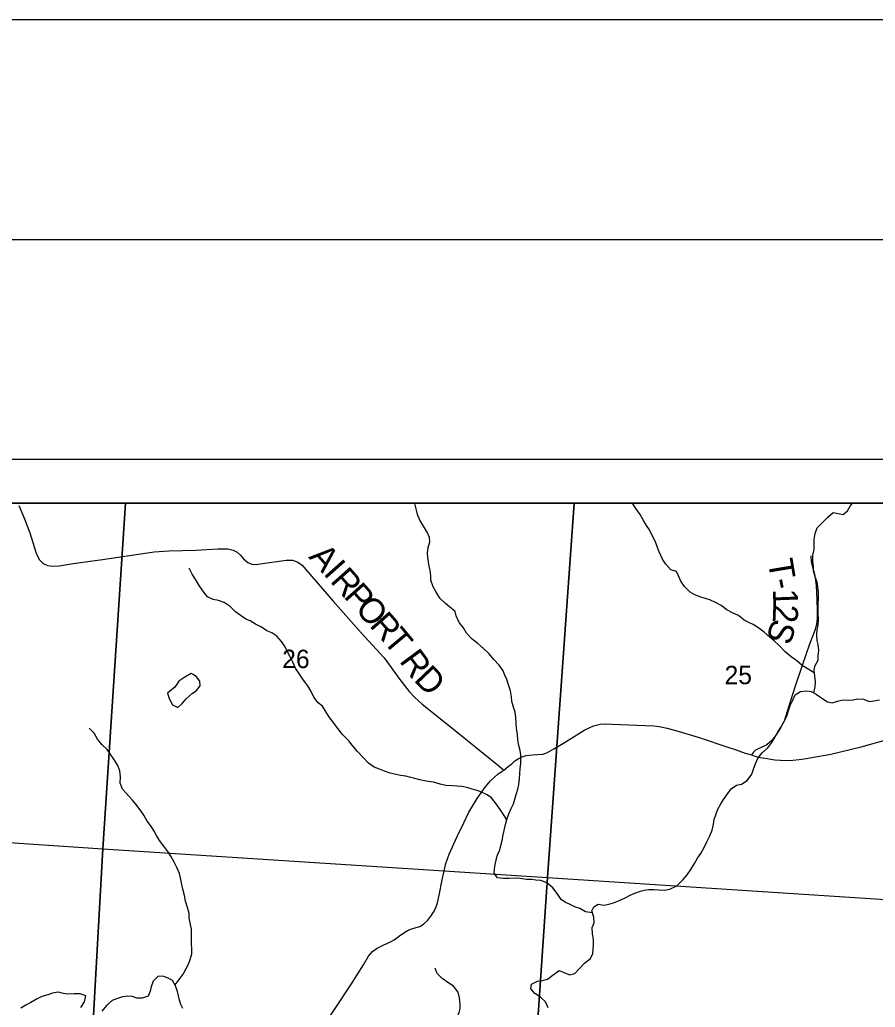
# Model space of a CAD drawing. Extents: x 0 to 34, y 0 to 22.
# Drawn here: x 3.268 to 5.215, y 19.753 to 22 of the extents above; entities that cross this region are included whole.
import ezdxf

# ---------------------------------------------------------------- set-up
doc = ezdxf.new("R2010")
doc.units = 0
for name, color, linetype in [('Default', 7, 'Continuous'), ('GM_X_County_Road', 7, 'Continuous'), ('GM_X_County_Road_Text', 7, 'Continuous'), ('GM_X_Major_River', 7, 'Continuous'), ('GM_X_Minor_Lake', 7, 'Continuous'), ('GM_X_Minor_River', 7, 'Continuous'), ('GM_X_Section', 7, 'Continuous'), ('GM_X_Section_Text', 7, 'Continuous'), ('GM_X_State_Route', 7, 'Continuous'), ('GM_X_Township_Road', 7, 'Continuous'), ('GM_X_Township_Road_Text', 7, 'Continuous'), ('SC_Scratch1', 7, 'Continuous'), ('SH_Border', 7, 'Continuous'), ('SH_Cut_Line', 7, 'Continuous'), ('SH_Data', 7, 'Continuous')]:
    doc.layers.add(name, color=color, linetype=linetype)

msp = doc.modelspace()

# ---------------------------------------------------------------- linework, layer by layer
at = {"layer": 'Default'}
for points in [[(3.5087, 20.9), (2.4999, 20.9), (2.446, 20.1823), (3.4572, 20.1141)], [(4.5292, 20.9), (3.5087, 20.9), (3.4572, 20.1141), (4.4687, 20.0485)], [(5.5445, 20.9), (4.5292, 20.9), (4.4687, 20.0485), (5.483, 19.983)]]:
    msp.add_lwpolyline(points, close=True, dxfattribs=at)
at = {"layer": 'GM_X_County_Road'}
msp.add_lwpolyline([(3.2658, 20.8947), (3.279, 20.8648), (3.2905, 20.8326), (3.3047, 20.7887), (3.3089, 20.7781), (3.3128, 20.7712), (3.3208, 20.7632), (3.3309, 20.7583), (3.342, 20.7567), (3.3576, 20.7579), (3.3896, 20.7629), (3.4561, 20.7721), (3.5736, 20.7892), (3.6077, 20.7921), (3.6686, 20.7933), (3.7197, 20.7965), (3.7413, 20.7965), (3.7533, 20.7935), (3.7623, 20.7889), (3.7699, 20.7818), (3.7768, 20.7738), (3.7867, 20.765), (3.7961, 20.7618), (3.8062, 20.7606), (3.8205, 20.7627), (3.8738, 20.7705), (3.8888, 20.7705), (3.8991, 20.7671), (3.9056, 20.7632), (3.9111, 20.7581), (3.9182, 20.7501), (3.9813, 20.6774), (4.0448, 20.6051), (4.097, 20.5485), (4.1326, 20.4989), (4.1538, 20.4719), (4.1667, 20.4579), (4.1839, 20.4429), (4.2511, 20.3889), (4.3578, 20.3024), (4.3692, 20.2929)], dxfattribs=at)
at = {"layer": 'GM_X_Major_River'}
for points in [[(4.4403, 19.7844), (4.4313, 19.7955), (4.4328, 19.8057), (4.4465, 19.8124), (4.4564, 19.8143), (4.469, 19.8176), (4.4819, 19.827), (4.4956, 19.8367), (4.51, 19.8306), (4.5198, 19.8275), (4.5309, 19.83), (4.5412, 19.841), (4.553, 19.8534), (4.5668, 19.8647), (4.5718, 19.8756), (4.573, 19.8859), (4.5734, 19.8961), (4.5739, 19.9082), (4.5713, 19.9208), (4.5703, 19.9352), (4.5749, 19.9458), (4.5746, 19.9583), (4.5701, 19.9724), (4.574, 19.9822), (4.5839, 19.9882), (4.5971, 19.9854), (4.6085, 19.988), (4.6192, 19.9913), (4.634, 19.9969), (4.6469, 20.0029), (4.6568, 20.0081), (4.6675, 20.0126), (4.6781, 20.0167), (4.6888, 20.0197), (4.6987, 20.0211), (4.7119, 20.0214), (4.7218, 20.0206), (4.7347, 20.0201), (4.7476, 20.0223), (4.7636, 20.0297), (4.7773, 20.044), (4.7869, 20.0546), (4.7949, 20.0671), (4.8034, 20.0803), (4.8106, 20.0927), (4.8175, 20.1033), (4.826, 20.1184), (4.8314, 20.1301), (4.8383, 20.1434), (4.8437, 20.1566), (4.8464, 20.1702), (4.848, 20.1805), (4.8519, 20.1914), (4.8565, 20.2043), (4.8631, 20.216), (4.8692, 20.2258), (4.8768, 20.2368), (4.8868, 20.2503), (4.899, 20.259), (4.9104, 20.2608), (4.9233, 20.269), (4.9337, 20.2838), (4.9379, 20.2951), (4.9433, 20.3095), (4.9487, 20.3208), (4.9575, 20.3321), (4.9701, 20.3434), (4.9793, 20.3555), (4.9881, 20.3702), (4.9939, 20.3804), (5.0008, 20.3914), (5.0069, 20.4027), (5.0134, 20.4156), (5.0173, 20.4284), (5.0208, 20.4398), (5.027, 20.4519), (5.0327, 20.464), (5.0445, 20.4718), (5.059, 20.4733), (5.0688, 20.4717), (5.0802, 20.4659), (5.093, 20.4563), (5.1062, 20.4479), (5.1164, 20.4463), (5.129, 20.4496), (5.1419, 20.4529), (5.1548, 20.4521), (5.1643, 20.4531), (5.1742, 20.4553), (5.1878, 20.4545), (5.2007, 20.4487), (5.2117, 20.4505), (5.2242, 20.4531)], [(4.4704, 19.7523), (4.4644, 19.7657), (4.4528, 19.7764), (4.4403, 19.7844)]]:
    msp.add_lwpolyline(points, dxfattribs=at)
at = {"layer": 'GM_X_Minor_Lake'}
for points in [[(3.6622, 20.5101), (3.6581, 20.5126), (3.6434, 20.5046), (3.6302, 20.4951), (3.6211, 20.4818), (3.6038, 20.4681)], [(3.6038, 20.4681), (3.6076, 20.456), (3.6156, 20.4416), (3.6277, 20.4352), (3.6375, 20.4447), (3.6462, 20.4553), (3.6602, 20.4671), (3.6704, 20.4744), (3.6787, 20.485), (3.6775, 20.4956), (3.6699, 20.5054), (3.6622, 20.5101)]]:
    msp.add_lwpolyline(points, dxfattribs=at)
at = {"layer": 'GM_X_Minor_River'}
for points in [[(4.5715, 19.9681), (4.5555, 19.9704), (4.5423, 19.978), (4.5328, 19.9813), (4.5191, 19.9878), (4.5097, 19.9915), (4.4998, 19.9987), (4.4907, 20.0123), (4.4808, 20.0252), (4.4675, 20.0362), (4.4538, 20.0418), (4.4421, 20.0425), (4.4323, 20.0437), (4.4209, 20.0444), (4.4069, 20.0466), (4.3955, 20.047), (4.3819, 20.0466), (4.3687, 20.0465), (4.3554, 20.0476), (4.3478, 20.0586), (4.3485, 20.0685), (4.35, 20.0779), (4.3523, 20.0882), (4.3545, 20.0977), (4.3601, 20.1117), (4.3627, 20.1212), (4.3657, 20.133), (4.368, 20.1455), (4.3706, 20.1557), (4.3732, 20.169), (4.3766, 20.1804), (4.3811, 20.1937), (4.3859, 20.2058), (4.3912, 20.216), (4.3946, 20.227), (4.3976, 20.2373), (4.4013, 20.2494), (4.4036, 20.2601), (4.405, 20.2741), (4.4061, 20.2847), (4.4068, 20.2965), (4.4083, 20.3082), (4.4083, 20.3177), (4.4079, 20.3275), (4.4067, 20.3378), (4.4036, 20.3488), (4.4013, 20.3609), (4.4005, 20.3745), (4.3986, 20.3878), (4.3978, 20.3988), (4.397, 20.4132), (4.3951, 20.4246), (4.3913, 20.4363), (4.3878, 20.4492), (4.387, 20.4594), (4.3847, 20.4734), (4.3809, 20.4848), (4.3763, 20.4988), (4.3721, 20.5091), (4.3683, 20.5189), (4.3591, 20.5318), (4.347, 20.5443), (4.3356, 20.5583), (4.3231, 20.5692), (4.3105, 20.5806), (4.2973, 20.5911), (4.2847, 20.6044), (4.2775, 20.6169), (4.268, 20.6286), (4.2607, 20.6438), (4.2584, 20.6536), (4.2459, 20.6642), (4.2364, 20.6721), (4.2243, 20.6835), (4.2155, 20.6975), (4.2087, 20.71), (4.2037, 20.7247), (4.2033, 20.735), (4.2017, 20.7471), (4.1998, 20.7566), (4.1979, 20.7664), (4.1963, 20.7763), (4.1956, 20.7865), (4.1974, 20.799), (4.2008, 20.8123), (4.2004, 20.8218), (4.195, 20.8343), (4.187, 20.8479), (4.1787, 20.8612), (4.1729, 20.8744), (4.1706, 20.8843), (4.1668, 20.8994), (4.1667, 20.9)], [(5.0761, 20.5142), (5.0618, 20.5229), (5.0485, 20.5312), (5.036, 20.5414), (5.0234, 20.5504), (5.0098, 20.5618), (4.9965, 20.5754), (4.9851, 20.5871), (4.9752, 20.5951), (4.9623, 20.6068), (4.9502, 20.6155), (4.9373, 20.6242), (4.927, 20.6287), (4.9164, 20.6343), (4.9039, 20.6446), (4.8918, 20.6502), (4.877, 20.6578), (4.8641, 20.6672), (4.8512, 20.674), (4.8387, 20.68), (4.8288, 20.683), (4.8178, 20.6864), (4.8042, 20.6917), (4.7939, 20.6981), (4.7807, 20.711), (4.7723, 20.7231), (4.7673, 20.7348), (4.7628, 20.7447), (4.7499, 20.7484), (4.7381, 20.7617), (4.7309, 20.773), (4.7232, 20.7893), (4.7194, 20.7996), (4.7148, 20.8121), (4.7087, 20.8234), (4.7007, 20.8393), (4.6943, 20.8492), (4.687, 20.8609), (4.6794, 20.8745), (4.6684, 20.89), (4.6623, 20.9)], [(5.0749, 20.4686), (5.0782, 20.4823), (5.0785, 20.4941), (5.0754, 20.5199), (5.0773, 20.5297), (5.0852, 20.5434), (5.0851, 20.5529), (5.0866, 20.5658), (5.0851, 20.5783), (5.0824, 20.5877), (5.0816, 20.6006), (5.0827, 20.612), (5.0849, 20.623), (5.0856, 20.6359), (5.0852, 20.6495), (5.0848, 20.662), (5.0848, 20.6715), (5.0858, 20.6837), (5.0854, 20.6969), (5.0843, 20.7098), (5.0823, 20.7204), (5.0777, 20.7329), (5.0743, 20.7462), (5.0743, 20.7557), (5.0731, 20.7686), (5.073, 20.7818), (5.076, 20.7947), (5.0756, 20.8076), (5.076, 20.8179), (5.0778, 20.8311), (5.0827, 20.844), (5.0951, 20.8562), (5.1072, 20.8687), (5.1189, 20.879), (5.1416, 20.8745), (5.1518, 20.8829), (5.1575, 20.8935), (5.1632, 20.9)], [(4.3763, 20.1796), (4.369, 20.1917), (4.3613, 20.2031), (4.3518, 20.2159), (4.3412, 20.2299), (4.3317, 20.2368), (4.3184, 20.2428), (4.3086, 20.2462), (4.2976, 20.2492), (4.2881, 20.2529), (4.2741, 20.2556), (4.2635, 20.2563), (4.2525, 20.257), (4.2378, 20.2581), (4.2249, 20.2611), (4.2093, 20.2653), (4.1931, 20.2679), (4.1787, 20.2709), (4.1673, 20.2735), (4.1578, 20.2758), (4.1461, 20.2791), (4.1347, 20.2806), (4.1245, 20.2829), (4.1105, 20.2863), (4.0976, 20.2908), (4.0866, 20.2953), (4.0745, 20.2994), (4.0616, 20.3085), (4.0487, 20.3221), (4.0365, 20.335), (4.024, 20.3497), (4.0164, 20.3596), (4.0027, 20.3743), (3.992, 20.3876), (3.9833, 20.3993), (3.9711, 20.4152), (3.9654, 20.425), (3.9571, 20.4387), (3.9472, 20.4462), (3.9369, 20.4591), (3.9312, 20.4716), (3.9236, 20.4845), (3.9137, 20.4973), (3.9046, 20.5113), (3.8955, 20.5246), (3.889, 20.5386), (3.884, 20.5492), (3.8779, 20.5602), (3.8718, 20.5734), (3.8635, 20.5855), (3.8532, 20.598), (3.8418, 20.6052), (3.8304, 20.6097), (3.8183, 20.618), (3.8047, 20.6252), (3.7921, 20.6324), (3.7827, 20.6365), (3.7698, 20.6456), (3.7591, 20.6531), (3.747, 20.6652), (3.7333, 20.6743), (3.7204, 20.6785), (3.7079, 20.6807), (3.6951, 20.6871), (3.6844, 20.7007), (3.6764, 20.7128), (3.6684, 20.7257), (3.6604, 20.739), (3.6536, 20.7522)], [(3.6214, 19.8044), (3.6305, 19.8169), (3.6395, 19.8283), (3.6467, 19.8416), (3.6519, 19.8514), (3.6553, 19.8617), (3.6591, 19.8746), (3.6594, 19.8875), (3.659, 19.8973), (3.659, 19.9072), (3.6585, 19.9197), (3.6585, 19.9311), (3.6558, 19.9451), (3.6535, 19.9572), (3.6531, 19.9667), (3.6496, 19.9807), (3.645, 19.9951), (3.6427, 20.008), (3.6393, 20.022), (3.6366, 20.033), (3.6339, 20.0478), (3.6312, 20.058), (3.6251, 20.0716), (3.619, 20.0834), (3.6118, 20.097), (3.6049, 20.1076), (3.5958, 20.1197), (3.5856, 20.1329), (3.5791, 20.1439), (3.5737, 20.1538), (3.5673, 20.1636), (3.5578, 20.1769), (3.5502, 20.1901), (3.5437, 20.2003), (3.535, 20.2113), (3.5247, 20.2245), (3.5019, 20.2495), (3.4962, 20.2631), (3.4973, 20.2779), (3.4957, 20.2916), (3.49, 20.3052), (3.482, 20.3177), (3.4736, 20.3302), (3.4664, 20.34), (3.455, 20.3514), (3.4451, 20.3635), (3.4371, 20.3771), (3.4261, 20.3885)], [(4.202, 19.6603), (4.206, 19.6727), (4.2101, 19.6837), (4.2184, 19.6974), (4.2259, 19.7114), (4.2372, 19.7232), (4.2505, 19.7232), (4.2629, 19.7278), (4.2682, 19.7411), (4.2701, 19.7506), (4.27, 19.7601), (4.2688, 19.7745), (4.2654, 19.7881), (4.2551, 19.801), (4.2419, 19.81), (4.229, 19.8187), (4.2179, 19.8304), (4.213, 19.8426)], [(3.639, 19.7502), (3.6345, 19.76), (3.6314, 19.7695), (3.6291, 19.7793), (3.6272, 19.7896), (3.6226, 19.8025), (3.6153, 19.8146), (3.6055, 19.8199), (3.5956, 19.8232), (3.5831, 19.8243), (3.5714, 19.8126), (3.5666, 19.8), (3.5647, 19.7902), (3.5602, 19.7784), (3.5466, 19.7742), (3.5345, 19.7742), (3.5242, 19.7776), (3.514, 19.7783), (3.5015, 19.7768), (3.4883, 19.7722), (3.4785, 19.7684), (3.4649, 19.7573), (3.4543, 19.7444)], [(3.4066, 19.753), (3.4149, 19.7659), (3.4182, 19.7792), (3.405, 19.7841), (3.3917, 19.7837), (3.3766, 19.7829), (3.3671, 19.7848), (3.355, 19.7874), (3.3421, 19.7851), (3.3315, 19.782), (3.3183, 19.7778), (3.3073, 19.7725), (3.2934, 19.7645), (3.2813, 19.7584), (3.2703, 19.7512)]]:
    msp.add_lwpolyline(points, dxfattribs=at)
at = {"layer": 'GM_X_Section'}
for points in [[(3.4572, 20.1141), (3.4007, 19.112), (3.378, 19.1131), (2.3838, 19.1776), (2.446, 20.1823)], [(4.4687, 20.0485), (4.4009, 19.0464), (4.3808, 19.0475), (3.4007, 19.112), (3.4572, 20.1141)], [(4.4687, 20.0485), (5.483, 19.983), (5.4174, 18.9797), (4.4009, 19.0464)]]:
    msp.add_lwpolyline(points, close=True, dxfattribs=at)
at = {"layer": 'GM_X_State_Route'}
for points in [[(4.3692, 20.2929), (4.3797, 20.3012), (4.3876, 20.3074), (4.3949, 20.3137), (4.4018, 20.3183), (4.4112, 20.3229), (4.4202, 20.3259), (4.4349, 20.3277), (4.446, 20.3286), (4.4579, 20.3293), (4.4676, 20.3323), (4.483, 20.3415), (4.5051, 20.3544), (4.5536, 20.3843), (4.5635, 20.3891), (4.5736, 20.3933), (4.589, 20.3976), (4.6003, 20.3983), (4.6162, 20.3976), (4.6537, 20.3962), (4.7107, 20.3935), (4.7232, 20.3921), (4.7409, 20.3884), (4.7682, 20.3808), (4.8138, 20.3673), (4.8819, 20.3443), (4.8958, 20.3395)], [(5.0528, 20.3185), (5.0705, 20.3213), (5.1135, 20.3295), (5.1825, 20.3456), (5.2536, 20.3659), (5.2734, 20.3716), (5.2856, 20.3737), (5.2946, 20.3742), (5.2999, 20.3742), (5.3091, 20.3739), (5.3309, 20.3703), (5.3413, 20.3689), (5.3509, 20.3675), (5.3578, 20.368), (5.3675, 20.3689), (5.3802, 20.3703), (5.4071, 20.3751), (5.4344, 20.379), (5.4957, 20.3859), (5.5145, 20.3877), (5.526, 20.39), (5.5385, 20.3944)], [(4.8958, 20.3395), (4.9189, 20.3316), (4.9334, 20.3277), (4.9477, 20.3226), (4.9695, 20.319), (4.9764, 20.3178), (4.9866, 20.3164), (4.9994, 20.3155), (5.0125, 20.315), (5.027, 20.3155), (5.042, 20.3169), (5.0528, 20.3185)], [(3.9187, 19.6494), (4.0213, 19.8045), (4.0498, 19.8496), (4.0616, 19.87), (4.0708, 19.8806), (4.0816, 19.8882), (4.0949, 19.8946), (4.1115, 19.9025), (4.12, 19.9071), (4.1324, 19.916), (4.1439, 19.9241), (4.1531, 19.9294), (4.1646, 19.9331), (4.178, 19.9372), (4.1865, 19.9427), (4.1966, 19.9519), (4.2037, 19.9607), (4.2097, 19.9699), (4.2138, 19.9779), (4.2182, 19.9913), (4.2221, 20.0085), (4.229, 20.0432), (4.2378, 20.0801), (4.2449, 20.1017), (4.2635, 20.1417), (4.2787, 20.1732), (4.2902, 20.1969), (4.3088, 20.2281), (4.3273, 20.2542), (4.3395, 20.2688), (4.3569, 20.2848), (4.3692, 20.2929)]]:
    msp.add_lwpolyline(points, dxfattribs=at)
at = {"layer": 'GM_X_Township_Road'}
msp.add_lwpolyline([(5.0685, 20.7806), (5.0687, 20.7664), (5.0721, 20.7544), (5.0756, 20.7415), (5.0781, 20.73), (5.0804, 20.7126), (5.0818, 20.6801), (5.0827, 20.656), (5.0827, 20.6378), (5.0811, 20.6244), (5.0772, 20.6106), (5.0654, 20.5798), (5.0484, 20.5308), (5.0316, 20.4814), (5.0178, 20.4386), (5.0073, 20.4041), (4.9994, 20.3891), (4.9905, 20.3753), (4.9792, 20.3606), (4.9682, 20.3507), (4.9424, 20.3385), (4.9376, 20.3337), (4.9334, 20.3277)], dxfattribs=at)
at = {"layer": 'SC_Scratch1'}
msp.add_lwpolyline([(5.53, 20.9), (2.1, 20.9), (2.1, 19.1982), (2.3572, 19.1804), (3.3448, 19.1146), (4.3628, 19.0495), (4.7394, 19.0241), (4.7997, 19.0196), (5.182, 18.9932), (5.4007, 18.9779), (5.4089, 19.0989), (5.4469, 19.6641), (5.4955, 20.3864)], close=True, dxfattribs=at)
at = {"layer": 'SH_Border'}
msp.add_lwpolyline([(1.5, 21.5), (33.5, 21.5), (33.5, 0.5), (1.5, 0.5)], close=True, dxfattribs=at)
at = {"layer": 'SH_Cut_Line'}
msp.add_lwpolyline([(0, 0), (34, 0), (34, 22), (0, 22)], close=True, dxfattribs=at)
at = {"layer": 'SH_Data'}
for p, q in [((2, 21), (9, 21)), ((2.1, 20.9), (8.9, 20.9))]:
    msp.add_line(p, q, dxfattribs=at)

# ---------------------------------------------------------------- texts
at = {"layer": 'GM_X_County_Road_Text'}
for s, rotation, p in [('A', 311.5851, (3.9238, 20.777)), ('I', 311.5813, (3.957, 20.7396)), ('R', 311.5832, (3.9725, 20.7222)), ('P', 311.5858, (4.0034, 20.6873)), ('O', 311.5824, (4.0289, 20.6586)), ('R', 311.4734, (4.062, 20.6212)), ('T', 309.9631, (4.0927, 20.5866)), ('R', 306.5186, (4.1301, 20.5408)), ('D', 313.6134, (4.1628, 20.4974))]:
    msp.add_text(s, height=0.0568, rotation=rotation, dxfattribs=at).set_placement(p)
at = {"layer": 'GM_X_Section_Text'}
for s, p in [('26', (3.8652, 20.525)), ('25', (4.8719, 20.4883))]:
    msp.add_text(s, height=0.04186, rotation=0, dxfattribs=at).set_placement(p)
at = {"layer": 'GM_X_Township_Road_Text'}
for s, rotation, p in [('T', 279.4539, (4.97, 20.7691)), ('-', 281.3048, (4.9774, 20.7252)), ('1', 272.1914, (4.9816, 20.7047)), ('2', 267.7722, (4.983, 20.6709)), ('S', 251.0857, (4.9824, 20.6402))]:
    msp.add_text(s, height=0.0568, rotation=rotation, dxfattribs=at).set_placement(p)

doc.saveas('drawing.dxf')
